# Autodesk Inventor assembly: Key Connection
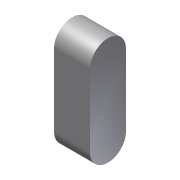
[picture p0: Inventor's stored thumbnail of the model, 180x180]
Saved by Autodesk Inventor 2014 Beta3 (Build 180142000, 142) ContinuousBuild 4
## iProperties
Created: 2011-01
Part Number: Key Connection
Document SubType Name: Assembly
Designer: Beta-8540w
ClientObjectVersion: 1
Author: Beta-8540w
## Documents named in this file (2)
- C:\Inventor 2014 Essentials\Assemblies\Chapter 09\Design Accelerators\Key Connection c09-01.iam
- C:\Inventor 2014 Essentials\Content Center Files\en-US\DIN 6885  A\DIN 6885 - A 4 x 4 x 12.ipt
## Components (1 placed, 1 different names)
1. DIN 6885 A A 4 x 4 x 12:1
